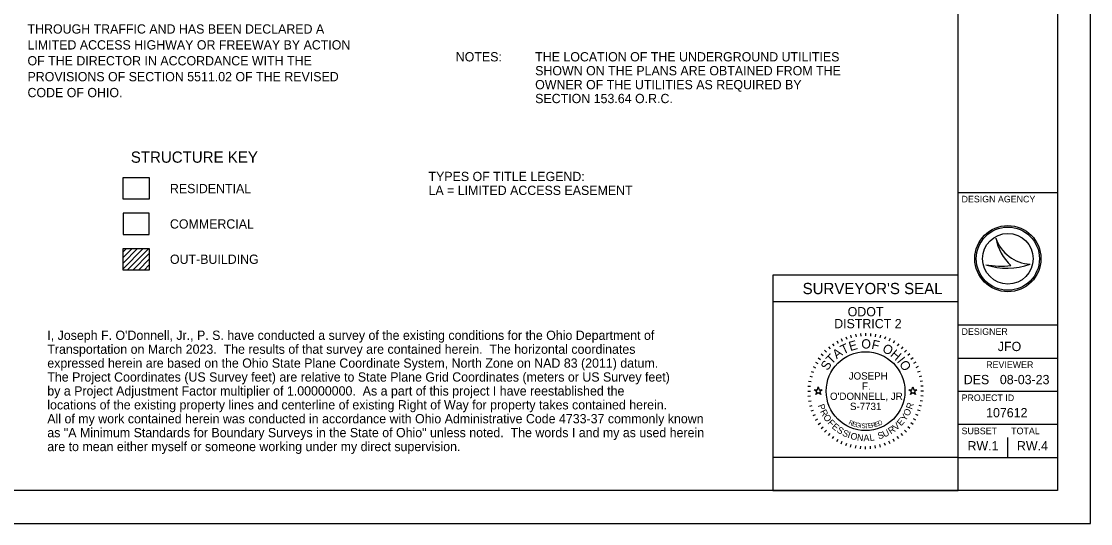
# Model space of a CAD drawing. Extents: x 0 to 34, y 0 to 22.
# Drawn here: x 17.84 to 34, y 0 to 7.58 of the extents above; entities that cross this region are included whole.
import ezdxf

# ---------------------------------------------------------------- set-up
doc = ezdxf.new("R2010")
doc.units = 0
for name, color, linetype in [('Default', 7, 'Continuous'), ('SC_Shading1', 7, 'Continuous'), ('SH_Border', 7, 'Continuous'), ('SH_Cut_Line', 7, 'Continuous'), ('SH_Data', 7, 'Continuous'), ('SH_Text', 7, 'Continuous')]:
    doc.layers.add(name, color=color, linetype=linetype)

msp = doc.modelspace()

# ---------------------------------------------------------------- linework, layer by layer
at = {"layer": 'Default'}
for points in [[(29.824, 2.02), (29.871, 2.02), (29.885, 2.065), (29.899, 2.02), (29.946, 2.02), (29.908, 1.992), (29.923, 1.948), (29.885, 1.975), (29.847, 1.948), (29.862, 1.992)], [(31.254, 2.02), (31.301, 2.02), (31.315, 2.065), (31.329, 2.02), (31.376, 2.02), (31.338, 1.992), (31.353, 1.948), (31.315, 1.975), (31.277, 1.948), (31.292, 1.992)]]:
    msp.add_lwpolyline(points, close=True, dxfattribs=at)
at = {"layer": 'SC_Shading1'}
msp.add_lwpolyline([(19.379, 4.364), (19.776, 4.364), (19.776, 4.69), (19.379, 4.69)], close=True, dxfattribs=at)
at = {"layer": 'SH_Border'}
for p, q in [((32, 0.5), (32, 21.5)), ((32, 5), (33.5, 5)), ((32, 3), (33.5, 3)), ((32, 2.5), (33.5, 2.5)), ((32, 2), (33.5, 2)), ((32, 1.5), (33.5, 1.5)), ((32, 1), (33.5, 1))]:
    msp.add_line(p, q, dxfattribs=at)
msp.add_lwpolyline([(1.5, 21.5), (33.5, 21.5), (33.5, 0.5), (1.5, 0.5)], close=True, dxfattribs=at)
at = {"layer": 'SH_Cut_Line'}
msp.add_lwpolyline([(0, 0), (34, 0), (34, 22), (0, 22)], close=True, dxfattribs=at)
at = {"layer": 'SH_Data'}
for p, q in [((32.567, 4.31), (32.567, 4.31)), ((32.417, 3.91), (32.417, 3.91)), ((32.75, 4), (32.75, 4)), ((33.087, 3.919), (33.087, 3.919)), ((32, 3.75), (29.2, 3.75)), ((29.2, 3.75), (29.2, 0.5)), ((32, 0.5), (32, 3.75)), ((32, 3.35), (29.2, 3.35)), ((30.163, 2.758), (30.183, 2.723)), ((30.23, 2.793), (30.247, 2.757)), ((30.301, 2.822), (30.314, 2.785)), ((30.374, 2.845), (30.384, 2.807)), ((30.448, 2.862), (30.455, 2.822)), ((30.524, 2.872), (30.527, 2.832)), ((30.6, 2.875), (30.6, 2.835)), ((30.676, 2.872), (30.673, 2.832)), ((30.752, 2.862), (30.745, 2.822)), ((30.826, 2.845), (30.816, 2.807)), ((30.899, 2.822), (30.886, 2.785)), ((30.97, 2.793), (30.953, 2.757)), ((31.037, 2.758), (31.017, 2.723)), ((29.981, 2.619), (30.01, 2.59)), ((30.038, 2.67), (30.063, 2.64)), ((30.098, 2.717), (30.121, 2.684)), ((31.102, 2.717), (31.079, 2.684)), ((31.162, 2.67), (31.137, 2.64)), ((31.219, 2.619), (31.19, 2.59)), ((29.842, 2.438), (29.877, 2.418)), ((29.883, 2.502), (29.916, 2.479)), ((29.93, 2.562), (29.96, 2.537)), ((31.27, 2.562), (31.24, 2.537)), ((31.317, 2.502), (31.284, 2.479)), ((31.358, 2.438), (31.323, 2.418)), ((29.778, 2.299), (29.815, 2.286)), ((29.807, 2.37), (29.843, 2.353)), ((31.393, 2.37), (31.357, 2.353)), ((31.422, 2.299), (31.385, 2.286)), ((29.738, 2.152), (29.778, 2.145)), ((29.755, 2.226), (29.793, 2.216)), ((31.445, 2.226), (31.407, 2.216)), ((31.462, 2.152), (31.422, 2.145)), ((29.725, 2), (29.765, 2)), ((29.728, 2.076), (29.768, 2.073)), ((31.472, 2.076), (31.432, 2.073)), ((31.475, 2), (31.435, 2)), ((29.728, 1.924), (29.768, 1.927)), ((29.738, 1.848), (29.778, 1.855)), ((29.755, 1.774), (29.793, 1.784)), ((31.445, 1.774), (31.407, 1.784)), ((31.462, 1.848), (31.422, 1.855)), ((31.472, 1.924), (31.432, 1.927)), ((29.778, 1.701), (29.815, 1.714)), ((29.807, 1.63), (29.843, 1.647)), ((31.393, 1.63), (31.357, 1.647)), ((31.422, 1.701), (31.385, 1.714)), ((29.842, 1.563), (29.877, 1.583)), ((29.883, 1.498), (29.916, 1.521)), ((29.93, 1.438), (29.96, 1.463)), ((31.27, 1.438), (31.24, 1.463)), ((31.317, 1.498), (31.284, 1.521)), ((31.358, 1.563), (31.323, 1.583)), ((29.981, 1.381), (30.01, 1.41)), ((30.038, 1.33), (30.063, 1.36)), ((30.098, 1.283), (30.121, 1.316)), ((31.102, 1.283), (31.079, 1.316)), ((31.162, 1.33), (31.137, 1.36)), ((31.219, 1.381), (31.19, 1.41)), ((32.75, 1), (32.75, 1.3)), ((30.163, 1.242), (30.183, 1.277)), ((30.23, 1.207), (30.247, 1.243)), ((30.301, 1.178), (30.314, 1.215)), ((30.374, 1.155), (30.384, 1.193)), ((30.448, 1.138), (30.455, 1.178)), ((30.524, 1.128), (30.527, 1.168)), ((30.6, 1.125), (30.6, 1.165)), ((30.676, 1.128), (30.673, 1.168)), ((30.752, 1.138), (30.745, 1.178)), ((30.826, 1.155), (30.816, 1.193)), ((30.899, 1.178), (30.886, 1.215)), ((30.97, 1.207), (30.953, 1.243)), ((31.037, 1.242), (31.017, 1.277)), ((32, 0.5), (29.2, 0.5))]:
    msp.add_line(p, q, dxfattribs=at)
msp.add_lwpolyline([(32, 0.5), (32, 1), (29.2, 1), (29.2, 0.5)], close=True, dxfattribs=at)
for centre, radius in [((32.75, 4), 0.5), ((32.75, 4), 0.477), ((32.75, 4), 0.477), ((32.75, 4), 0.382), ((30.6, 2), 0.595)]:
    msp.add_circle(centre, radius, dxfattribs=at)
for centre, radius, start, end in [((33.116, 4.498), 0.58, 198.9257, 198.9319), ((33.347, 4.47), 0.796, 191.6379, 191.6421), ((33.116, 4.498), 0.58, 198.9319, 267.1657), ((33.347, 4.47), 0.796, 191.6421, 226.0947), ((32.739, 4.87), 1.013, 251.4576, 290.0832), ((32.648, 5.154), 1.266, 259.4964, 259.4995), ((32.739, 4.87), 1.013, 251.4527, 251.4576), ((32.648, 5.154), 1.266, 259.4995, 276.6672)]:
    msp.add_arc(centre, radius, start, end, dxfattribs=at)
at = {"layer": 'SH_Text'}
for p, q in [((19.379, 4.153), (19.381, 4.155)), ((19.379, 4.103), (19.431, 4.155)), ((19.379, 4.018), (19.516, 4.155)), ((19.379, 3.934), (19.6, 4.155)), ((19.379, 3.849), (19.685, 4.155)), ((19.444, 3.829), (19.77, 4.155)), ((19.528, 3.829), (19.776, 4.077)), ((19.613, 3.829), (19.776, 3.992)), ((19.698, 3.829), (19.776, 3.907)), ((19.379, 3.833), (19.384, 3.829))]:
    msp.add_line(p, q, dxfattribs=at)
for points in [[(19.379, 5.225), (19.776, 5.225), (19.776, 4.899), (19.379, 4.899)], [(19.379, 4.155), (19.776, 4.155), (19.776, 3.829), (19.379, 3.829)]]:
    msp.add_lwpolyline(points, close=True, dxfattribs=at)

# ---------------------------------------------------------------- texts
at = {"layer": 'SH_Data'}
for s, height, p in [('DESIGN AGENCY', 0.1, (32.05, 4.85)), ("SURVEYOR'S SEAL", 0.17, (29.648, 3.465)), ('ODOT', 0.14, (30.329, 3.13)), ('DISTRICT 2', 0.14, (30.125, 2.95)), ('DESIGNER', 0.1, (32.05, 2.85)), ('JFO', 0.14, (32.598, 2.605)), ('REVIEWER', 0.1, (32.422, 2.35)), ('JOSEPH', 0.11, (30.345, 2.175)), ('F.', 0.11, (30.546, 2.022)), ('DES', 0.14, (32.083, 2.105)), ('08-03-23', 0.14, (32.629, 2.105)), ("O'DONNELL, JR.", 0.11, (30.062, 1.868)), ('PROJECT ID', 0.1, (32.05, 1.85)), ('S-7731', 0.11, (30.364, 1.715)), ('107612', 0.14, (32.421, 1.605)), ('SUBSET', 0.1, (32.05, 1.35)), ('TOTAL', 0.1, (32.8, 1.35)), ('RW.1', 0.14, (32.14, 1.105)), ('RW.4', 0.14, (32.887, 1.105))]:
    msp.add_text(s, height=height, dxfattribs=at).set_placement(p)
for s, height, rotation, p in [('E', 0.14, 15.7571, (30.368, 2.604)), ('O', 0.14, 359.7812, (30.535, 2.644)), ('F', 0.14, 347.4362, (30.681, 2.642)), ('A', 0.14, 36.4747, (30.163, 2.478)), ('T', 0.14, 25.7167, (30.262, 2.552)), ('O', 0.14, 332.2586, (30.84, 2.602)), ('H', 0.14, 319.9136, (30.963, 2.536)), ('S', 0.14, 57.1924, (30.028, 2.301)), ('T', 0.14, 46.4344, (30.088, 2.396)), ('I', 0.14, 308.367, (31.066, 2.448)), ('O', 0.14, 303.1491, (31.102, 2.409)), ('P', 0.1, 289.7431, (29.875, 1.784)), ('R', 0.1, 70.983, (31.301, 1.717)), ('R', 0.1, 296.9802, (29.909, 1.693)), ('O', 0.1, 304.7158, (29.953, 1.608)), ('Y', 0.1, 55.5058, (31.2, 1.54)), ('O', 0.1, 62.7428, (31.25, 1.613)), ('F', 0.1, 312.956, (30.019, 1.516)), ('E', 0.1, 319.6885, (30.081, 1.45)), ('S', 0.1, 326.9255, (30.155, 1.389)), ('R', 0.07, 334.487, (30.337, 1.505)), ('E', 0.07, 341.04, (30.391, 1.48)), ('G', 0.07, 347.4752, (30.441, 1.462)), ('I', 0.07, 353.7858, (30.509, 1.447)), ('S', 0.07, 356.8926, (30.536, 1.443)), ('T', 0.07, 3.0061, (30.586, 1.439)), ('E', 0.07, 6.0117, (30.639, 1.441)), ('R', 0.07, 11.9184, (30.692, 1.447)), ('E', 0.07, 17.6836, (30.75, 1.46)), ('D', 0.07, 23.3052, (30.801, 1.477)), ('R', 0.1, 33.296, (30.981, 1.347)), ('V', 0.1, 41.0316, (31.061, 1.401)), ('E', 0.1, 48.2687, (31.137, 1.467)), ('S', 0.1, 334.1626, (30.236, 1.337)), ('I', 0.1, 341.3997, (30.319, 1.298)), ('O', 0.1, 345.1351, (30.362, 1.282)), ('N', 0.1, 353.3752, (30.466, 1.255)), ('A', 0.1, 1.1108, (30.569, 1.244)), ('L', 0.1, 8.3479, (30.666, 1.247)), ('S', 0.1, 18.3234, (30.8, 1.271)), ('U', 0.1, 25.5604, (30.883, 1.299))]:
    msp.add_text(s, height=height, rotation=rotation, dxfattribs=at).set_placement(p)
at = {"layer": 'SH_Text'}
for s, height, p in [('THROUGH TRAFFIC AND HAS BEEN DECLARED A', 0.14, (17.936, 7.399)), ('LIMITED ACCESS HIGHWAY OR FREEWAY BY ACTION', 0.14, (17.936, 7.159)), ('NOTES:', 0.14, (24.407, 6.979)), ('THE LOCATION OF THE UNDERGROUND UTILITIES', 0.14, (25.607, 6.979)), ('OF THE DIRECTOR IN ACCORDANCE WITH THE', 0.14, (17.936, 6.919)), ('PROVISIONS OF SECTION 5511.02 OF THE REVISED', 0.14, (17.936, 6.679)), ('SHOWN ON THE PLANS ARE OBTAINED FROM THE', 0.14, (25.607, 6.769)), ('OWNER OF THE UTILITIES AS REQUIRED BY', 0.14, (25.607, 6.559)), ('CODE OF OHIO.', 0.14, (17.936, 6.439)), ('SECTION 153.64 O.R.C.', 0.14, (25.607, 6.349)), ('STRUCTURE KEY', 0.17, (19.497, 5.449)), ('TYPES OF TITLE LEGEND:', 0.14, (23.995, 5.172)), ('RESIDENTIAL', 0.14, (20.088, 4.989)), ('LA = LIMITED ACCESS EASEMENT', 0.14, (23.995, 4.962)), ('COMMERCIAL', 0.14, (20.088, 4.455)), ('OUT-BUILDING', 0.14, (20.088, 3.922)), ("I, Joseph F. O'Donnell, Jr., P. S. have conducted a survey of the existing conditions for the Ohio Department of", 0.14, (18.235, 2.774)), ('Transportation on March 2023.  The results of that survey are contained herein.  The horizontal coordinates', 0.14, (18.235, 2.564)), ('expressed herein are based on the Ohio State Plane Coordinate System, North Zone on NAD 83 (2011) datum.', 0.14, (18.235, 2.354)), ('The Project Coordinates (US Survey feet) are relative to State Plane Grid Coordinates (meters or US Survey feet)', 0.14, (18.235, 2.144)), ('by a Project Adjustment Factor multiplier of 1.00000000.  As a part of this project I have reestablished the', 0.14, (18.235, 1.934)), ('locations of the existing property lines and centerline of existing Right of Way for property takes contained herein.  ', 0.14, (18.235, 1.724)), ('All of my work contained herein was conducted in accordance with Ohio Administrative Code 4733-37 commonly known', 0.14, (18.235, 1.514)), ('as "A Minimum Standards for Boundary Surveys in the State of Ohio" unless noted.  The words I and my as used herein', 0.14, (18.235, 1.304)), ('are to mean either myself or someone working under my direct supervision.', 0.14, (18.235, 1.094))]:
    msp.add_text(s, height=height, dxfattribs=at).set_placement(p)

doc.saveas('drawing.dxf')
